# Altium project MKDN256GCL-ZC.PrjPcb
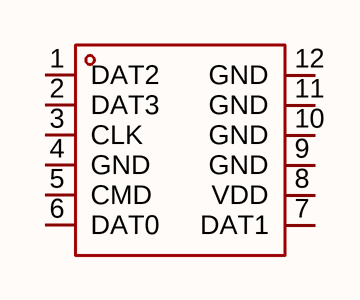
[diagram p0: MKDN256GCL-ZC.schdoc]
1 sheet, 1 parts. Net scope: global (net labels, ports and power ports of the same name join across sheets).

## Sheet MKDN256GCL-ZC.schdoc
size 127 x 101 mm

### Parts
U?  mkdn256gcl-zc  [LGA-16_L13.0-W9.0-P1.27-TL]  (value not drawn)

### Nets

Not connected (* = marked no-connect by the designer): U? 1(DAT2) 2(DAT3) 3(CLK) 4(GND) 5(CMD) 6(DAT0) 7(DAT1) 8(VDD) 9(GND) 10(GND) 11(GND) 12(GND)

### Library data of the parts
U? = mkdn256gcl-zc: 存储容量:256Gbit;时钟频率(fc):208MHz;工作电压:2.7V~3.6V;; Manufacturer: MK(米客方德); AddInBom: yes; Interface: SD接口; Clock Frequency: 208MHz; Standby Supply Current: 90uA; ECC: 有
